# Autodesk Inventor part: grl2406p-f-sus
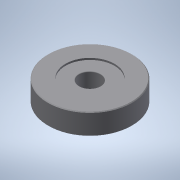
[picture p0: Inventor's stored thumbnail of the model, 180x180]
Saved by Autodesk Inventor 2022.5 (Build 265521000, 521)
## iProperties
Created: 2016-12
Part Number: grl2406p-f-sus
Material: 一般
Document SubType Name: Modeling
Designer: imaocorp
Density: 1 g/cm^3
Appearance: 既定
Author: imaocorp
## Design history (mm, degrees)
node "grl2406p-f-sus.x_t1"
node "grl2406p-f-sus"
node "Base1"
